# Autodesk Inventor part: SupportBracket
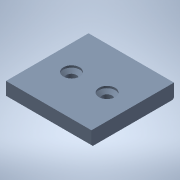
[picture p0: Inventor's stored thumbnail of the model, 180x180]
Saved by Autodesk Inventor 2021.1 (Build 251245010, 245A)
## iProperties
Created: 2005-11
Part Number: SupportBracket
Document SubType Name: Modeling
Designer: Administrator
Manufacturer: Standard
Standards Organization: Custom
Material: Generic
Density: 1 g/cm^3
Appearance: Light Steel Blue
Author: Administrator
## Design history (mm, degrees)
sketch "Sketch1"
  geometry: L1 (0, 0)-(30, 0); L2 (30, 0)-(30, -29); L3 (30, -29)-(0, -29); L4 (0, -29)-(0, 0)
  constraints: 8 end point, 2 parallel, 1 horizontal, 1 perpendicular
  dimensions: "d0" = 30 distance of L1.end L1.start; "d1" = 29 distance of L3.end L1.start
extrude "Extrusion1" new body sketch "Sketch1" distance "d2" = 5; taper "d3" = 0 deg
sketch "Sketch4"
  geometry: L1 (0, 0)-(30, 0) reference; L2 (0, -29)-(0, 0) reference; L3 (30, -29)-(0, -29) reference; L4 (30, 0)-(30, -29) reference; L5 (0, -14.5)-(30, -14.5); L6 (15, -29)-(15, 0); C1 r 1.414 at (8.75, -14.75); C2 r 1.414 at (21.25, -14.75)
  constraints: 4 end point, 4 midpoint, 2 centre point, 1 symmetric about line, 1 other
  dimensions: "d19" = 12.5 distance of C2.centre C1.centre
hole "Hole2" sketch "Sketch4" at (8.75, -14.75), (21.25, -14.75) diameter "d20" = 3.5; stored, may be unused: countersink angle "d24" = 90 deg, drill point angle "d26" = 118 deg; dims "d21" = 6, "d22" = 6, "d23" = 2, "d25" = 8
hole "Hole5" diameter "d47" = 5.7; stored, may be unused: countersink angle "d51" = 90 deg, drill point angle "d53" = 0 deg; dims "d45" = 10, "d46" = 10, "d48" = 6, "d49" = 4, "d50" = 2, "d52" = 0.7
hole "Hole6" diameter "d56" = 5.7; stored, may be unused: countersink angle "d60" = 90 deg, drill point angle "d62" = 0 deg; dims "d54" = 10, "d55" = 10, "d57" = 6, "d58" = 4, "d59" = 2, "d61" = 0.7
hole "Hole7" diameter "d68" = 3.5; stored, may be unused: countersink angle "d72" = 90 deg, drill point angle "d74" = 118 deg; dims "d66" = 10, "d67" = 10, "d69" = 6, "d70" = 5.7, "d71" = 2, "d73" = 8
hole "Hole8" diameter "d77" = 3.5; stored, may be unused: countersink angle "d81" = 90 deg, drill point angle "d83" = 118 deg; dims "d75" = 10, "d76" = 10, "d78" = 6, "d79" = 5.7, "d80" = 2, "d82" = 8
chamfer "Chamfer3" distance "d84" = 0.5; stored, may be unused: second distance "d85" = 2, angle "d86" = 45 deg
body "Solid1"
